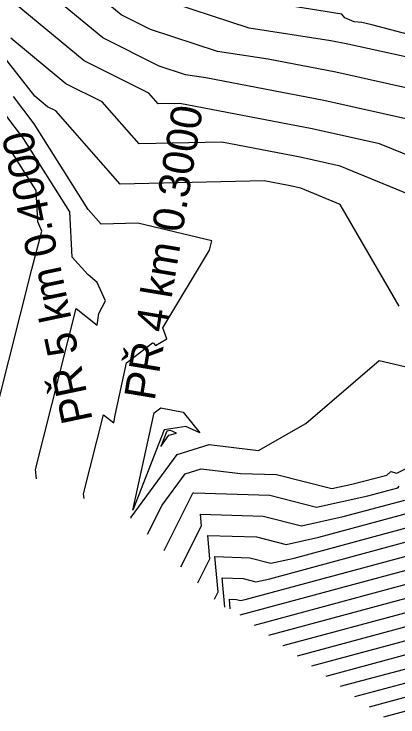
# Model space of a CAD drawing. Extents: x -549394 to -546608, y -1037055 to -1033629.
# Drawn here: x -547954.3 to -547841.9, y -1035853.5 to -1035648 of the extents above; entities that cross this region are included whole.
import ezdxf

# ---------------------------------------------------------------- set-up
doc = ezdxf.new("R2010")
doc.units = 0
for name, color, linetype in [('hlavni_vrst', 7, 'Continuous'), ('norm_vrst', 7, 'Continuous'), ('x_popis_pricne_rezy_C11', 7, 'Continuous')]:
    doc.layers.add(name, color=color, linetype=linetype)

msp = doc.modelspace()

# ---------------------------------------------------------------- linework, layer by layer
at = {"layer": 'hlavni_vrst'}
for p, q in [((-547858.39, -1035648.03), (-547876.12, -1035645.25)), ((-547857.52, -1035649.11), (-547858.39, -1035648.03)), ((-547854.74, -1035650.24), (-547857.52, -1035649.11)), ((-547852.54, -1035650.43), (-547854.74, -1035650.24)), ((-547849.55, -1035651.2), (-547852.54, -1035650.43)), ((-547814.63, -1035660.41), (-547849.55, -1035651.2)), ((-547939.12, -1035668.38), (-547955.26, -1035655.06)), ((-547928.46, -1035673.71), (-547939.12, -1035668.38)), ((-547917.65, -1035685.98), (-547928.46, -1035673.71)), ((-547893.46, -1035685.43), (-547917.65, -1035685.98)), ((-547870.53, -1035689.84), (-547893.46, -1035685.43)), ((-547858.83, -1035692.44), (-547870.53, -1035689.84)), ((-547821.55, -1035707.76), (-547858.83, -1035692.44)), ((-547842.22, -1035782.18), (-547814.62, -1035768.56)), ((-547904.22, -1035782.39), (-547899.49, -1035780.91)), ((-547899.49, -1035780.91), (-547888.03, -1035782.27)), ((-547845.23, -1035782.81), (-547844.01, -1035781.76)), ((-547844.01, -1035781.76), (-547842.22, -1035782.18)), ((-547910.98, -1035791.6), (-547904.22, -1035782.39)), ((-547888.03, -1035782.27), (-547877.49, -1035782.59)), ((-547877.49, -1035782.59), (-547861.3, -1035786.74)), ((-547855.43, -1035785.44), (-547845.23, -1035782.81)), ((-547861.3, -1035786.74), (-547855.43, -1035785.44)), ((-547915.25, -1035800.09), (-547910.98, -1035791.6)), ((-547879.45, -1035813.07), (-547833.99, -1035800.81)), ((-547892.6, -1035821.39), (-547893.39, -1035812.83)), ((-547893.39, -1035812.83), (-547887.27, -1035813.01)), ((-547887.27, -1035813.01), (-547883.54, -1035813.97)), ((-547883.54, -1035813.97), (-547879.45, -1035813.07)), ((-547875.51, -1035832.59), (-547824.03, -1035818.71)), ((-547854.51, -1035847.51), (-547814.07, -1035836.61))]:
    msp.add_line(p, q, dxfattribs=at)
at = {"layer": 'norm_vrst'}
for p, q in [((-547922.94, -1035648.21), (-547930.82, -1035641.7)), ((-547885.43, -1035652.08), (-547916.99, -1035641.76)), ((-547933.73, -1035661.65), (-547956.34, -1035642.99)), ((-547928.33, -1035654.93), (-547943.58, -1035642.34)), ((-547914.4, -1035652.48), (-547922.94, -1035648.21)), ((-547948.24, -1035672.03), (-547966.27, -1035648.96)), ((-547861.54, -1035655.82), (-547885.43, -1035652.08)), ((-547894.75, -1035658.91), (-547914.4, -1035652.48)), ((-547911.8, -1035663.2), (-547928.33, -1035654.93)), ((-547856.64, -1035656.76), (-547861.54, -1035655.82)), ((-547835.62, -1035661.44), (-547856.64, -1035656.76)), ((-547879.87, -1035661.23), (-547894.75, -1035658.91)), ((-547914.88, -1035671.09), (-547933.73, -1035661.65)), ((-547860.11, -1035665.03), (-547879.87, -1035661.23)), ((-547904.07, -1035665.73), (-547911.8, -1035663.2)), ((-547951.53, -1035684.39), (-547966.27, -1035664.95)), ((-547898.2, -1035666.65), (-547904.07, -1035665.73)), ((-547863.58, -1035673.3), (-547898.2, -1035666.65)), ((-547824.21, -1035673.02), (-547860.11, -1035665.03)), ((-547948.36, -1035680.11), (-547954.42, -1035672.11)), ((-547944.51, -1035675.1), (-547948.24, -1035672.03)), ((-547912.07, -1035674.27), (-547914.88, -1035671.09)), ((-547905.8, -1035674.13), (-547912.07, -1035674.27)), ((-547867.05, -1035681.57), (-547905.8, -1035674.13)), ((-547835.75, -1035679.5), (-547863.58, -1035673.3)), ((-547942.05, -1035676.33), (-547944.51, -1035675.1)), ((-547923.23, -1035697.69), (-547942.05, -1035676.33)), ((-547932.56, -1035705.15), (-547948.36, -1035680.11)), ((-547847.29, -1035685.97), (-547867.05, -1035681.57)), ((-547937.99, -1035705.85), (-547951.53, -1035684.39)), ((-547814.62, -1035699.39), (-547847.29, -1035685.97)), ((-547947.81, -1035699.61), (-547954.71, -1035688.66)), ((-547881.11, -1035696.74), (-547923.23, -1035697.69)), ((-547874, -1035698.11), (-547881.11, -1035696.74)), ((-547947.29, -1035708.7), (-547947.81, -1035699.61)), ((-547870.37, -1035698.92), (-547874, -1035698.11)), ((-547858.8, -1035703.67), (-547870.37, -1035698.92)), ((-547841.58, -1035733.38), (-547858.8, -1035703.67)), ((-547928.81, -1035709.4), (-547932.56, -1035705.15)), ((-547937.24, -1035719.08), (-547937.99, -1035705.85)), ((-547946.2, -1035711.49), (-547947.29, -1035708.7)), ((-547918.06, -1035709.16), (-547928.81, -1035709.4)), ((-547896.38, -1035714.31), (-547918.06, -1035709.16)), ((-547949.04, -1035722.57), (-547946.2, -1035711.49)), ((-547897.13, -1035717.01), (-547896.38, -1035714.31)), ((-547910.72, -1035739.72), (-547897.13, -1035717.01)), ((-547932.67, -1035724.17), (-547937.24, -1035719.08)), ((-547962.13, -1035774.01), (-547949.04, -1035722.57)), ((-547929.97, -1035726.44), (-547932.67, -1035724.17)), ((-547927.57, -1035731.87), (-547929.97, -1035726.44)), ((-547929.5, -1035735.52), (-547927.57, -1035731.87)), ((-547948.04, -1035781.15), (-547936.08, -1035734.1)), ((-547936.08, -1035734.1), (-547930, -1035738.92)), ((-547930, -1035738.92), (-547929.5, -1035735.52)), ((-547909.56, -1035742.92), (-547910.72, -1035739.72)), ((-547921.39, -1035749.97), (-547913.8, -1035744.11)), ((-547913.8, -1035744.11), (-547913.49, -1035744.17)), ((-547913.49, -1035744.17), (-547912.91, -1035744.88)), ((-547912.91, -1035744.88), (-547909.56, -1035742.92)), ((-547924.74, -1035765.25), (-547921.39, -1035749.97)), ((-547868.91, -1035767.73), (-547847.42, -1035749.31)), ((-547847.42, -1035749.31), (-547833.59, -1035752.53)), ((-547913.24, -1035764.59), (-547911.36, -1035763.14)), ((-547911.36, -1035763.14), (-547904.84, -1035764.34)), ((-547933.96, -1035788.29), (-547928.07, -1035765.12)), ((-547928.07, -1035765.12), (-547925.07, -1035767.49)), ((-547925.07, -1035767.49), (-547924.74, -1035765.25)), ((-547919.49, -1035793.06), (-547913.24, -1035764.59)), ((-547904.84, -1035764.34), (-547899.9, -1035770.4)), ((-547904.01, -1035768.61), (-547910.31, -1035769.54)), ((-547899.9, -1035770.4), (-547904.01, -1035768.61)), ((-547882.72, -1035775.55), (-547868.91, -1035767.73)), ((-547910.31, -1035769.54), (-547919.49, -1035793.06)), ((-547909.58, -1035769.9), (-547911.36, -1035774.46)), ((-547911.36, -1035774.46), (-547908.94, -1035771.15)), ((-547908.49, -1035769.73), (-547909.58, -1035769.9)), ((-547908.94, -1035771.15), (-547906.78, -1035770.48)), ((-547906.78, -1035770.48), (-547908.49, -1035769.73)), ((-547906.58, -1035776.77), (-547897.16, -1035773.84)), ((-547897.16, -1035773.84), (-547882.72, -1035775.55)), ((-547920.03, -1035795.1), (-547906.58, -1035776.77)), ((-547947.71, -1035783.87), (-547948.04, -1035781.15)), ((-547850.76, -1035788.87), (-547841.96, -1035786.5)), ((-547841.96, -1035786.5), (-547841.56, -1035785.99)), ((-547933.79, -1035789.63), (-547933.96, -1035788.29)), ((-547910.34, -1035804.84), (-547901.93, -1035788.1)), ((-547901.93, -1035788.1), (-547901.86, -1035788)), ((-547901.86, -1035788), (-547901.82, -1035787.99)), ((-547901.82, -1035787.99), (-547901.7, -1035788)), ((-547901.7, -1035788), (-547879.45, -1035788.67)), ((-547879.45, -1035788.67), (-547865.75, -1035792.19)), ((-547865.75, -1035792.19), (-547850.76, -1035788.87)), ((-547857.93, -1035794.92), (-547839.97, -1035790.08)), ((-547865.1, -1035800.97), (-547837.97, -1035793.66)), ((-547920.15, -1035795.35), (-547920.03, -1035795.1)), ((-547899.43, -1035797.62), (-547899.74, -1035794.21)), ((-547899.74, -1035794.21), (-547881.4, -1035794.76)), ((-547881.4, -1035794.76), (-547870.19, -1035797.63)), ((-547870.19, -1035797.63), (-547857.93, -1035794.92)), ((-547905.43, -1035809.58), (-547899.43, -1035797.62)), ((-547872.28, -1035807.02), (-547835.98, -1035797.24)), ((-547896.99, -1035807.29), (-547897.62, -1035800.41)), ((-547897.62, -1035800.41), (-547883.36, -1035800.84)), ((-547883.36, -1035800.84), (-547874.64, -1035803.08)), ((-547874.64, -1035803.08), (-547865.1, -1035800.97)), ((-547886.62, -1035819.12), (-547832, -1035804.39)), ((-547900.53, -1035814.32), (-547896.99, -1035807.29)), ((-547894.56, -1035816.95), (-547895.51, -1035806.62)), ((-547895.51, -1035806.62), (-547885.32, -1035806.93)), ((-547888.11, -1035823.63), (-547830, -1035807.97)), ((-547885.32, -1035806.93), (-547879.09, -1035808.52)), ((-547879.09, -1035808.52), (-547872.28, -1035807.02)), ((-547883.91, -1035826.62), (-547828.01, -1035811.55)), ((-547879.71, -1035829.6), (-547826.02, -1035815.13)), ((-547895.62, -1035819.06), (-547894.56, -1035816.95)), ((-547891.01, -1035821.89), (-547891.27, -1035819.04)), ((-547891.27, -1035819.04), (-547889.23, -1035819.1)), ((-547889.23, -1035819.1), (-547887.99, -1035819.42)), ((-547887.99, -1035819.42), (-547886.62, -1035819.12)), ((-547871.31, -1035835.57), (-547822.04, -1035822.29)), ((-547867.11, -1035838.56), (-547820.04, -1035825.87)), ((-547862.91, -1035841.54), (-547818.05, -1035829.45)), ((-547858.71, -1035844.53), (-547816.06, -1035833.03)), ((-547850.31, -1035850.49), (-547812.07, -1035840.19)), ((-547846.11, -1035853.48), (-547810.08, -1035843.77))]:
    msp.add_line(p, q, dxfattribs=at)

# ---------------------------------------------------------------- texts
at = {"layer": 'x_popis_pricne_rezy_C11'}
for s, rotation, p in [('PŘ 4 km 0.3000', 80.5677, (-547913.18, -1035761.28)), ('PŘ 5 km 0.4000', 101.8343, (-547931.24, -1035766.69))]:
    msp.add_text(s, height=9.0627, rotation=rotation, dxfattribs=at).set_placement(p)

doc.saveas('drawing.dxf')
